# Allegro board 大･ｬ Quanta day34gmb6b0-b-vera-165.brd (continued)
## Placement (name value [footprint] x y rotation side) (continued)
PC76  *22U/6.3V_8  [CC0805]  103.4 51.36 0 top
PC77  0.1U/10V_4  [CC0402]  69.24 45.26 270 top
PC78  *10U/6.3V_6  [CC0603]  67.84 44.37 270 top
PC79  0.1U/10V_4  [CC0402]  66.19 44.12 180 top
PC80  *0.1U/10V_4  [CC0402]  63.27 42.09 0 top
PC82  1000P/50V_4  [CC0402]  70.76 41.45 180 top
PC85  0.1U/10V_4  [CC0402]  63.27 40.95 0 top
PC86  1000P/50V_4  [CC0402]  70.76 40.44 180 top
PC87  *0.1U/10V_4  [CC0402]  63.27 39.93 0 top
PC90  0.1U/25V_4  [CC0402]  94.77 45.64 180 top
PC92  0.1U/10V_4  [CC0402]  65.56 38.02 90 top
PC93  *10U/6.3V_6  [CC0603]  95.02 42.98 0 top
PC95  *10U/6.3V_6  [CC0603]  67.71 37.77 90 top
PC96  0.1U/10V_4  [CC0402]  69.24 37.64 90 top
PC98  10U/6.3V_6  [CC0603]  93.8 41.2 0 top
PC101  0.1U/10V_4  [CC0402]  69.24 34.85 270 top
PC103  *10U/6.3V_6  [CC0603]  67.71 34.09 270 top
PC104  0.1U/10V_4  [CC0402]  65.43 33.71 270 top
PC105  1U/6.3V_4  [CC0402]  102.21 38.68 180 top
PC106  0.033U/10V_4  [CC0402]  92.78 38.66 0 top
PC107  0.1U/10V_4  [CC0402]  92.78 37.64 0 top
PC108  *0.1U/10V_4  [CC0402]  63.27 31.8 0 top
PC109  1000P/50V_4  [CC0402]  69.75 31.29 180 top
PC110  0.1U/10V_4  [CC0402]  63.27 30.79 0 top
PC111  1000P/50V_4  [CC0402]  69.75 30.28 180 top
PC112  *0.1U/10V_4  [CC0402]  63.27 29.77 0 top
PC113  *0.1U/10V_4  [CC0402]  95.12 35.23 90 top
PC114  *0.1U/10V_4  [CC0402]  98.58 35.23 90 top
PC115  0.1U/10V_4  [CC0402]  65.56 27.86 90 top
PC116  *10U/6.3V_6  [CC0603]  67.71 27.61 90 top
PC117  0.1U/10V_4  [CC0402]  69.24 27.1 90 top
PC118  2200P/50V_4  [CC0402]  89.58 181.58 90 bottom
PC119  0.1U/50V_6  [CC0603]  89.53 179.26 270 bottom
PC124  10U/25V_8  [CC0805]  120.52 177.6 90 bottom
PC126  0.1U/25V_4  [CC0402]  121.03 179.91 180 bottom
PC127  0.1U/25V_4  [CC0402]  124.23 181.38 90 bottom
PC128  10U/25V_8  [CC0805]  118.41 177.62 90 bottom
PC130  0.1U/25V_4  [CC0402]  116.76 177.8 90 bottom
PC164  22U/6.3V_8  [CC0805]  115.34 113.21 270 bottom
PC165  22U/6.3V_8  [CC0805]  117.37 113.21 270 bottom
PC166  *22U/6.3V_8  [CC0805]  112.6 112.5 0 bottom
PC167  *100U/25V  [ECAP6D3S]  181.68 123.5 270 bottom
PC168  *2200P/50V_4  [CC0402]  112.29 98.86 180 bottom
PC169  4.7U/25V_8  [CC0805]  100.48 91.75 270 top
PC170  *4.7U/25V_8  [CC0805]  102.51 91.75 270 top
PC171  0.1U/25V_4  [CC0402]  98.96 90.98 270 bottom
PC172  2200P/50V_4  [CC0402]  102.89 85.98 180 bottom
PC173  0.01U/25V_4  [CC0402]  93.88 86.16 90 bottom
PC174  0.01U/50V_4  [CC0402]  95.65 85.65 0 bottom
PC175  22U/6.3V_8  [CC0805]  182.93 78 270 bottom
PC176  *22U/6.3V_8  [CC0805]  190.14 78.16 270 bottom
PC177  22U/6.3V_8  [CC0805]  188.11 78.16 270 bottom
PC178  22U/6.3V_8  [CC0805]  186.08 78.16 270 bottom
PC179  0.1U/10V_4  [CC0402]  184.45 77.62 270 bottom
PC180  0.1U/25V_4  [CC0402]  191.16 72.82 90 bottom
PC181  1U/6.3V_4  [CC0402]  193.57 71.68 90 bottom
PC182  0.1U/10V_4  [CC0402]  194.59 71.68 270 bottom
PC183  *0.1U/10V_4  [CC0402]  198.25 67.49 270 bottom
PC184  *2200P/50V_4  [CC0402]  188.62 66.6 0 bottom
PC185  4.7U/25V_8  [CC0805]  193.44 64.19 0 bottom
PC186  *150U/6.3V_5X3.8 ESR20  [ECAP5X5_8-5_9-2P]  185.57 63.68 90 bottom
PC187  0.1U/25V_4  [CC0402]  48.16 58.22 90 bottom
PC188  0.1U/25V_4  [CC0402]  53.24 58.09 90 bottom
PC189  0.1U/25V_4  [CC0402]  41.04 57.71 180 bottom
PC190  *100U/25V  [ECAP6D3S]  35.82 57.03 0 bottom
PC191  2200P/50V_4  [CC0402]  41.04 56.69 180 bottom
PC192  2200P/50V_4  [CC0402]  48.16 55.04 180 bottom
PC193  4.7U/25V_8  [CC0805]  42.06 54.92 0 bottom
PC194  0.1U/25V_4  [CC0402]  94.03 57.91 180 bottom
PC195  0.1U/25V_4  [CC0402]  48.16 54.03 180 bottom
PC196  4.7U/25V_8  [CC0805]  42.06 52.88 0 bottom
PC197  4.7U/25V_8  [CC0805]  97.36 56.67 180 bottom
PC198  4.7U/6.3V_6  [CC0603]  56.79 52.5 0 bottom
PC199  *2200P/50V_4  [CC0402]  38.48 52.3 0 bottom
PC200  0.1U/25V_4  [CC0402]  33.68 52.25 180 bottom
PC201  *150U/6.3V_5X3.8 ESR20  [ECAP5X5_8-5_9-2P]  102.54 40.31 90 bottom
PC202  4.7U/25V_8  [CC0805]  47.76 51.72 90 bottom
PC203  4.7U/25V_8  [CC0805]  49.79 51.72 90 bottom
PC204  0.01U/50V_4  [CC0402]  56.54 51.36 180 bottom
PC205  4.7U/6.3V_6  [CC0603]  44.98 49.96 90 bottom
PC206  *2200P/50V_4  [CC0402]  46.12 49.84 90 bottom
PC207  4.7U/25V_8  [CC0805]  95.58 54.66 180 bottom
PC208  22U/6.3V_8  [CC0805]  102.06 53.57 0 bottom
PC209  *0.1U/10V_4  [CC0402]  56.54 48.31 0 bottom
PC210  0.1U/25V_4  [CC0402]  97.51 58.27 0 bottom
PC211  *0.1U/10V_4  [CC0402]  40.28 47.04 180 bottom
PC212  2200P/50V_4  [CC0402]  95.91 58.73 90 bottom
PC213  0.1U/25V_4  [CC0402]  57.43 46.79 90 bottom
PC214  6800P/50V_4  [CC0402]  44.02 46.53 90 bottom
PC215  22U/6.3V_8  [CC0805]  103.27 51.56 0 bottom
PC216  2.2U/6.3V_6  [CC0603]  45.12 46.28 270 bottom
PC217  *2200P/50V_4  [CC0402]  102.33 49.53 90 bottom
PC218  *150U/6.3V_5X3.8 ESR20  [ECAP5X5_8-5_9-2P]  46.76 40.31 90 bottom
PC219  *150U/6.3V_5X3.8 ESR20  [ECAP5X5_8-5_9-2P]  41.3 40.3 90 bottom
PC220  0.1U/10V_4  [CC0402]  29.74 39.68 270 bottom
PC221  22U/6.3V_8  [CC0805]  31.27 39.55 90 bottom
PC222  22U/6.3V_8  [CC0805]  33.3 39.55 90 bottom
PC223  *22U/6.3V_8  [CC0805]  37.54 39.55 90 bottom
PC224  22U/6.3V_8  [CC0805]  35.33 39.55 90 bottom
PC225  22U/6.3V_8  [CC0805]  57.17 38.28 90 bottom
PC226  22U/6.3V_8  [CC0805]  52.86 38.28 90 bottom
PC227  22U/6.3V_8  [CC0805]  55.01 38.28 90 bottom
PC228  *22U/6.3V_8  [CC0805]  50.57 38.28 90 bottom
PC229  0.1U/10V_4  [CC0402]  58.82 38.02 270 bottom
PC230  0.1U/10V_4  [CC0402]  101.01 56.26 0 bottom
PC231  0.1U/25V_4  [CC0402]  79.88 172.34 180 bottom
PC232  100P/50V_4  [CC0402]  86.63 179.86 0 top
PC233  *0.1U/50V_6  [CC0603]  86.86 181.27 0 top
PC234  0.047U/25V_4  [CC0402]  95.19 181.13 0 top
PC235  2200P/50V_4  [CC0402]  108.91 180.85 270 top
PC236  0.1U/25V_4  [CC0402]  92 173.48 180 top
PC237  0.1U/25V_4  [CC0402]  88.74 174.86 0 top
PC238  0.1U/25V_4  [CC0402]  91 174.5 0 top
PC239  1U/25V_4  [CC0402]  94.28 177.58 270 top
PC240  0.1U/25V_4  [CC0402]  92.4 183.95 180 top
PC241  0.1U/25V_4  [CC0402]  104.56 186.16 0 top
PC242  1000P/50V_4  [CC0402]  104.55 185.14 180 top
PC243  2200P/50V_4  [CC0402]  104.52 184.1 180 top
PC244  0.01U/50V_4  [CC0402]  102.05 178.19 270 bottom
PC250  2200P/50V_4  [CC0402]  53.82 162 270 top
PC251  0.1U/10V_4  [CC0402]  55.04 167.97 180 top
PC252  *10U/6.3V_6  [CC0603]  58.37 163.68 180 top
PC253  0.1U/10V_4  [CC0402]  58.52 162.38 180 top
PC254  100U/25V  [ECAP6D3S]  98.5 168.05 90 bottom
PD1  PDZ5.6B  [DSM]  119.77 184.11 180 top
PD2  PDZ5.6B  [DSM]  119.77 182.08 180 top
PD4  RB501V-40  [DSM]  97.78 179.17 270 top
PD7  1N4448WS-7-F  [DSM]  67.9 179.6 0 bottom
PD8  RB501V-40  [DSM]  103.45 176.12 270 bottom
PD9  SMAJ20A-13-F  [D-DO-214AC]  80.11 174.22 0 bottom
PD10  SMAJ20A-13-F  [D-DO-214AC]  45.36 56.19 270 bottom
PD11  UDZVTE-173.6B  [DSM]  57.2 53.65 180 top
PJP1  *POWER_JP/S  [SHORT-SOLDERJUMPER-3]  180.52 77.42 135 bottom
PJP2  *POWER_JP/S  [SHORT-SOLDERJUMPER-3]  103.78 56.06 45 bottom
PJP3  *POWER_JP/S  [SHORT-SOLDERJUMPER-3]  29.95 43.25 135 bottom
PJP4  *POWER_JP/S  [SHORT-SOLDERJUMPER-3]  58.32 42.22 45 bottom
PL1  *80/5A  [RC0805]  172.36 121.34 270 top
PL2  1uH/2.6A_2520  [L3_2X2_5-1_55]  183.41 66.22 180 top
PL3  *0_8/S  [SHORT0805]  196.75 62.03 180 top
PL4  *0_8/S  [SHORT0805]  69.11 183.69 180 bottom
PL5  *0_8/S  [SHORT0805]  121.72 183.54 180 bottom
PL6  *0_8/S  [SHORT0805]  69.11 181.66 180 bottom
PL7  *0_8/S  [SHORT0805]  121.72 181.51 180 bottom
PL8  4.7uH/5.5A(PCMC063T-4R7MN)  [CHOKE-MPL73-1R5]  109.36 176.84 0 bottom
PL14  0.36uH  [CHOKE-ETQP4L]  112.29 105.72 0 bottom
PL15  *0_8/S  [SHORT0805]  102 87.68 180 bottom
PL16  1uH/11A(PCMC063T-1R0MN)  [CHOKE-MPL73-1R5]  186.33 72.19 180 bottom
PL17  *0_8/S  [SHORT0805]  43.08 57.71 270 bottom
PL18  *0_8/S  [SHORT0805]  50.95 57.71 270 bottom
PL19  *0_8/S  [SHORT0805]  94 56.67 0 bottom
PL20  2.2uH/8A(PCMC063T-2R2MN)  [CHOKE-MPL73-1R5]  35.58 47.3 270 bottom
PL21  1.5uH/9A(PCMC063T-1R5MN)  [CHOKE-MPL73-1R5]  53.24 44.25 270 bottom
PL22  1uH/11A(PCMC063T-1R0MN)  [CHOKE-MPL73-1R5]  96.29 45.01 0 bottom
PQ1  DMN601K-7  [SOT23_213-3_3-2]  115.37 181.82 90 top
PQ5  DMN601K-7  [SOT23_213-3_3-2]  175.79 130.35 180 top
PQ6  BSS138W  [UMT_213-3-1_3]  171.6 128.58 180 top
PQ9  *DMN601K-7  [SOT23_213-3_3-2]  171.47 125.4 0 top
PQ10  FDMC8884  [PG-TSDSON-8-8P-R]  175.28 121.84 270 top
PQ12  DRC5144E0L  [UMT_213-3-1_3]  39.9 98.32 270 top
PQ13  DRC5144E0L  [UMT_213-3-1_3]  42.54 98.25 90 top
PQ14  *DRC5144E0L  [UMT_213-3-1_3]  37.23 98.22 90 top
PQ15  *FDMS0308AS  [SO-8FL-5P]  108.13 97.09 180 top
PQ16  *2N7002KDW  [SC70-2_1-65-6P]  37.36 94.29 270 top
PQ17  *2N7002KDW  [SC70-2_1-65-6P]  42.82 94.29 270 top
PQ18  *DRC5144E0L  [UMT_213-3-1_3]  47.14 94.29 90 top
PQ19  *FDMS7698  [SO-8FL-5P]  106.84 89.05 90 top
PQ20  QM3016D  [TO252_134-9_9-4_57-SMT]  78.99 179.12 0 bottom
PQ29  FDMS0308AS  [SO-8FL-5P]  108.13 97.07 180 bottom
PQ30  FDMS7698  [SO-8FL-5P]  106.83 89.05 90 bottom
PQ31  FDMC7692S  [PG-TSDSON-8-8P-R]  97.92 51.16 90 bottom
PQ32  FDMC8884  [PG-TSDSON-8-8P-R]  94.16 51.08 270 bottom
PQ33  EMB20P03V  [PG-TSDSON-8-8P-R]  72.97 180.85 0 bottom
PQ34  DMN601K-7  [SOT23_213-3_3-2]  81.68 178.62 270 top
PQ35  METR3904-G  [SOT23_213-3_3-2]  77.92 178.64 90 top
PQ36  FDMC8884  [PG-TSDSON-8-8P-R]  102.28 179.63 0 top
PQ37  FDMC8884  [PG-TSDSON-8-8P-R]  106.55 180.01 90 top
PQ38  MMDT2907A-7-F  [SOT363-2_1-65-6P]  70.79 176.35 90 bottom
PQ39  FDMS7698  [SO-8FL-5P]  96.81 179.38 0 bottom
PQ40  METR3904-G  [SOT23_213-3_3-2]  59.33 56.46 180 top
PQ41  *DMN601K-7  [SOT23_213-3_3-2]  46.33 162.97 270 top
PQ42  DRC5144E0L  [UMT_213-3-1_3]  43.28 159.11 270 top
PQ43  EMB32N03K  [TSOP6-2_8-95]  54.18 165.1 180 top
PQ44  DMN601K-7  [SOT23_213-3_3-2]  50.09 161.06 270 top
PR1  330_4  [RC0402]  124.48 186.74 0 top
PR2  330_4  [RC0402]  126.64 186.74 180 top
PR3  1K/F_4  [RC0402]  128.29 186.23 90 top
PR4  200K_4  [RC0402]  129.69 186.23 270 top
PR7  470_8  [RC0805]  119.91 180.14 0 top
PR9  4.02K/F_4  [RC0402]  101.9 175.08 90 bottom
PR11  22_8  [RC0805]  97.18 183.52 0 top
PR12  10/F_4  [RC0402]  86.66 178.82 180 top
PR13  *0_4/S  [SHORT0402]  85.82 176.56 270 top
PR14  2.2_6  [RC0603]  109.02 178.38 90 top
PR15  *0_4/S  [SHORT0402]  86.84 176.56 270 top
PR16  430K/F_4  [RC0402]  84.53 181 180 top
PR17  88.7K/F_4  [RC0402]  84.55 179.88 0 top
PR18  43.2K/F_4  [RC0402]  88.03 176.56 90 top
PR19  0_6  [RC0603]  95.43 179.6 0 top
PR20  1M_4  [RC0402]  81.51 176.02 0 top
PR21  1M_4  [RC0402]  81.51 174.98 0 top
PR22  4.02K/F_4  [RC0402]  92.89 181.53 90 bottom
PR52  1M_4  [RC0402]  172.74 131.5 180 top
PR55  1M_4  [RC0402]  172.74 130.48 0 top
PR56  2M_4  [RC0402]  174.01 127.31 90 top
PR57  1M_4  [RC0402]  175.03 127.31 270 top
PR61  *22_8  [RC0805]  170.33 121.34 270 top
PR62  *1M_4  [RC0402]  35.33 97.59 270 top
PR63  *0_4/S  [SHORT0402]  44.47 96.06 90 top
PR64  *1M_4  [RC0402]  40.54 94.79 180 top
PR65  *1M_4  [RC0402]  35.33 95.56 270 top
PR66  *1M_4  [RC0402]  40.54 95.81 180 top
PR67  *0_4/S  [SHORT0402]  39.52 93.78 180 top
PR68  2.43K/F_6  [RC0603]  44.47 93.65 90 top
PR69  2.43K/F_6  [RC0603]  41.12 92.99 270 top
PR70  1_6  [RC0603]  95.78 88.82 270 top
PR71  16.2K/F_4  [RC0402]  91.72 88.7 0 top
PR72  *0_4/S  [SHORT0402]  95.65 83.36 180 bottom
PR73  *0_4/S  [SHORT0402]  91.72 87.68 180 top
PR74  1K/F_4  [RC0402]  98.83 87.68 180 top
PR75  10/F_4  [RC0402]  88.92 86.41 0 top
PR76  *0_4/S  [SHORT0402]  98.83 86.41 0 top
PR77  *10K/F_4  [RC0402]  100.86 86.41 180 top
PR78  54.9/F_4  [RC0402]  98.83 85.4 0 top
PR79  *0_4/S  [SHORT0402]  100.86 85.4 0 top
PR80  64.9K/F_6  [RC0603]  87.15 85.14 270 top
PR81  *75/F_4  [RC0402]  98.83 84.38 0 top
PR82  *0_4/S  [SHORT0402]  100.86 84.38 0 top
PR83  130/F_4  [RC0402]  98.83 83.36 0 top
PR84  *0_4/S  [SHORT0402]  100.86 83.36 0 top
PR85  165K/F_4  [RC0402]  87.15 82.73 90 top
PR86  *0_4/S  [SHORT0402]  98.83 82.35 0 top
PR87  *75/F_4  [RC0402]  100.86 82.35 0 top
PR88  23.7K/F_4  [RC0402]  91.59 81.46 0 bottom
PR89  *0_4/S  [SHORT0402]  98.83 81.33 0 top
PR90  75K/F_4  [RC0402]  86.13 81.33 270 top
PR91  *0_4  [RC0402]  98.83 80.32 180 top
PR92  15.4K/F_4  [RC0402]  88.92 82.22 180 top
PR93  18.7K/F_4  [RC0402]  93.24 81.46 90 bottom
PR94  1K/F_4  [RC0402]  92.23 78.66 90 top
PR95  49.9/F_4  [RC0402]  93.24 78.66 90 top
PR96  0_4  [RC0402]  94.26 78.66 90 top
PR97  2.2_6  [RC0603]  98.58 78.41 90 top
PR98  6.04K/F_4  [RC0402]  90.19 77.65 270 top
PR99  0_4  [RC0402]  91.72 76.12 0 top
PR100  0_4  [RC0402]  96.29 76.63 90 top
PR101  0_4  [RC0402]  97.31 76.63 90 top
PR102  *0_4  [RC0402]  197 67.28 0 top
PR103  100K/F_4  [RC0402]  197.25 65.58 180 top
PR104  *0_6/S  [SHORT0603]  183.11 63.73 180 top
PR105  100K/F_4  [RC0402]  190.02 62.28 0 top
PR106  *0_4/S  [SHORT0402]  192.09 62.28 0 top
PR107  *0_4/S  [SHORT0402]  190.02 61.14 0 top
PR108  150K/F_4  [RC0402]  192.17 61.14 0 top
PR109  *0_2/S  [SHORT0201]  181.63 68.05 90 top
PR110  *0_4/S  [SHORT0402]  57.25 50.29 0 top
PR111  10K/F_4  [RC0402]  57.25 49.28 0 top
PR112  *0_4/S  [SHORT0402]  57.25 48.26 180 top
PR113  *0_4/S  [SHORT0402]  63.26 43.16 180 top
PR114  *0_8/S  [SHORT0805]  70.38 43.1 180 top
PR117  *0_6/S  [SHORT0603]  70 39.29 0 top
PR118  *0_4/S  [SHORT0402]  63.27 38.91 0 top
PR119  2.2_6  [RC0603]  95.02 44.37 180 top
PR122  301K/F_4  [RC0402]  102.21 39.7 0 top
PR123  *0_2/S  [SHORT0201]  93.83 39.65 180 top
PR124  *0_4/S  [SHORT0402]  63.27 32.82 180 top
PR125  *0_8/S  [SHORT0805]  70.38 32.82 180 top
PR126  100/F_4  [RC0402]  94.31 38.15 270 top
PR127  *0_2/S  [SHORT0201]  101.67 37.52 90 top
PR128  10.2K/F_4  [RC0402]  92.22 35.87 0 top
PR129  *0_4/S  [SHORT0402]  93.8 35.23 90 top
PR130  *0_4/S  [SHORT0402]  99.59 35.23 90 top
PR131  620K/F_4  [RC0402]  100.61 35.23 270 top
PR132  *0_4/S  [SHORT0402]  102.13 35.23 90 top
PR133  *0_6/S  [SHORT0603]  70 29.01 0 top
PR134  10K/F_4  [RC0402]  92.22 34.72 0 top
PR135  *0_4/S  [SHORT0402]  63.27 28.75 0 top
PR136  *0_2/S  [SHORT0201]  114.78 176.4 270 bottom
PR137  RC1206-R010  [F3_2X1_65-2_8]  114.91 177.09 90 bottom
PR138  *0_2/S  [SHORT0201]  114.78 177.85 90 bottom
PR143  12.4K/F_4  [RC0402]  62.76 182.04 180 bottom
PR144  75K/F_4  [RC0402]  64.87 181.94 0 bottom
PR158  *0_2/S  [SHORT0201]  109.62 105.84 180 bottom
PR159  *0_2/S  [SHORT0201]  114.96 105.84 0 bottom
PR160  220K_4 NTC  [RC0402]  105.18 102.29 90 bottom
PR161  *2.2_6  [RC0603]  112.29 99.97 0 bottom
PR162  TSM0B104F4251RZ  [RC0402]  110.51 92.89 270 bottom
PR163  69.8K/F_4  [RC0402]  91.59 84.51 180 bottom
PR164  100K/F_4  [RC0402]  91.59 83.49 0 bottom
PR165  0_6  [RC0603]  192.3 73.08 90 bottom
PR166  *0_4/S  [SHORT0402]  197.25 69.01 180 bottom
PR167  *0_2/S  [SHORT0201]  196.62 67.87 270 bottom
PR168  *2.2_6  [RC0603]  188.62 67.87 180 bottom
PR169  *0_4/S  [SHORT0402]  198.25 65.35 90 bottom
PR170  *0_2/S  [SHORT0201]  188.11 76.51 90 bottom
PR171  3.16K/F_4  [RC0402]  195.73 64.19 90 bottom
PR172  10.2K/F_4  [RC0402]  196.75 64.19 90 bottom
PR173  499K/F_4  [RC0402]  55.27 55.42 180 bottom
PR174  150K/F_4  [RC0402]  55.27 54.41 0 bottom
PR175  0_6  [RC0603]  31.77 52.25 90 bottom
PR176  *2.2_6  [RC0603]  36.07 52.17 0 bottom
PR177  1K/F_4  [RC0402]  56.54 50.34 180 bottom
PR178  0_6  [RC0603]  58.19 49.58 270 bottom
PR179  1M_4  [RC0402]  56.54 49.33 180 bottom
PR180  *2.2_6  [RC0603]  48.28 46.79 180 bottom
PR181  *0_4/S  [SHORT0402]  41.81 46.53 270 bottom
PR182  1K/F_4  [RC0402]  43.01 46.54 90 bottom
PR183  1M_4  [RC0402]  40.28 46.03 0 bottom
PR184  1K/F_4  [RC0402]  40.28 45.01 0 bottom
PR185  *1K/F_4  [RC0402]  42.31 45.01 180 bottom
PR186  *2.2_6  [RC0603]  100.35 50.09 270 bottom
PR187  *0_2/S  [SHORT0201]  43.31 43.74 180 bottom
PR188  *0_2/S  [SHORT0201]  58.82 39.68 180 bottom
PR189  *0_2/S  [SHORT0201]  104.67 54.15 180 bottom
PR206  1M_4  [RC0402]  72.64 174.7 90 bottom
PR207  220K_4  [RC0402]  69.06 176.35 270 bottom
PR208  1K_6  [RC0603]  67.84 178 0 bottom
PR209  220K_4  [RC0402]  67.89 176.4 270 bottom
PR210  1M_4  [RC0402]  72.64 176.76 270 bottom
PR211  RC1206-R010  [F3_2X1_65-2_8]  96.14 174.09 270 bottom
PR212  4.02K/F4  [RC0402]  90.77 184.49 270 top
PR213  69.8K/F_4  [RC0402]  82.49 181.27 0 top
PR214  100K/F_4  [RC0402]  89.12 176.55 90 top
PR215  127K/F_4  [RC0402]  80.26 181.27 0 top
PR216  750K/F_4  [RC0402]  78.13 181.29 180 top
PR217  100K/F_4  [RC0402]  89.1 184 0 top
PR218  100K/F_4  [RC0402]  89.1 185.04 0 top
PR219  5.6/F_6  [RC0603]  90.35 176.32 90 top
PR220  10/F_6  [RC0603]  91.62 176.37 90 top
PR221  *0_2/S  [SHORT0201]  96.01 174.73 90 bottom
PR222  *0_2/S  [SHORT0201]  96.01 173.46 270 bottom
PR223  4.99K/F_4  [RC0402]  56.13 55.93 180 top
PR224  4.02K/F_4  [RC0402]  56.13 56.95 0 top
PR237  *22_8  [RC0805]  46.3 166.47 0 top
PR245  1M_4  [RC0402]  45.39 159.84 90 top
PR246  1M_4  [RC0402]  46.61 159.84 90 top
PR247  1M_4  [RC0402]  50.09 164.54 90 top
PR248  5.1M_4  [RC0402]  52.63 162 90 top
PU1  BQ24738H  [PVQFN20-3_5X3_5-5-25P]  90.96 180.62 180 top
PU3  NCP81101MNTXG  [QFN28-4X4-4-29P-NCP81101MNTWG]  93.62 84 180 top
PU4  APW8824  [TSOP6-2_8-95]  187.22 63.81 90 top
PU5  APL3523A  [SON14-3X2-4-15P]  66.7 40.95 270 top
PU7  RT8231BGQW  [WQFN20-3X3-4-21P]  97.86 39.68 270 top
PU8  APL3523A  [SON14-3X2-4-15P]  66.7 30.79 270 top
PU10  G5335AQT1U  [QFN23-4X4-5]  193.42 67.95 180 bottom
PU11  SY8208B  [QFN10-3X3-45]  52.98 50.6 180 bottom
PU12  SY8208C  [QFN10-3X3-45]  41.93 49.71 90 bottom
Q1  DDTC144EUA-7-F  [UMT_213-3-1_3]  25.04 171.88 180 top
Q3  2N7002DW  [SC70-2_1-65-6P]  192.94 159.19 0 top
Q4  DRC5144E0L  [UMT_213-3-1_3]  170.69 155.98 90 top
Q5  *DRC5144E0L  [UMT_213-3-1_3]  173.35 155.98 90 top
Q10  2N7002  [SOT23_213-3_3-2]  19.94 94.36 0 top
Q12  2N7002DW  [SC70-2_1-65-6P]  181 90.7 0 top
Q13  2N7002K  [SOT23_213-3_3-2]  36.98 90.22 180 top
Q14  2N7002DW  [SC70-2_1-65-6P]  25.4 87.78 180 top
Q15  METR3904-G  [SOT23_213-3_3-2]  56.03 86.92 270 top
Q16  METR3904-G  [SOT23_213-3_3-2]  33.04 81.71 90 top
Q17  ME2303T1  [SOT23_213-3_3-2]  190.4 79.05 180 top
Q18  2N7002E  [SOT23_213-3_3-2]  190.65 73.84 270 top
Q19  2N7002  [SOT23_213-3_3-2]  178.08 63.81 0 top
Q20  AO3404  [SOT23_213-3_3-2]  166.65 135.81 0 top
Q21  2N7002  [SOT23_213-3_3-2]  169.7 131.88 270 top
Q22  2N7002K  [SOT23_213-3_3-2]  22.12 37.9 180 top
Q23  *METR3904-G  [SOT23_213-3_3-2]  108.48 23.42 90 top
Q24  2N7002  [SOT23_213-3_3-2]  138.58 22.53 0 top
Q25  2N7002K  [SOT23_213-3_3-2]  147.6 21.9 270 top
Q26  DRC5144E0L  [UMT_213-3-1_3]  143.15 21.64 270 top
Q27  2N7002KDW  [SC70-2_1-65-6P]  160.81 20.88 180 top
Q28  *DRC5144E0L  [UMT_213-3-1_3]  37.84 15.19 180 top
Q29  *MMBT3904  [SOT23_213-3_3-2]  171.35 9.58 270 top
Q30  *DRC5144E0L  [UMT_213-3-1_3]  37.97 8.92 270 top
Q31  2N7002  [SOT23_213-3_3-2]  176.15 6.66 270 top
Q34  2N7002DW  [SC70-2_1-65-6P]  168.43 9.58 90 top
Q37  2N7002K  [SOT23_213-3_3-2]  195.2 101.17 90 top
Q38  *2N7002DW  [SC70-2_1-65-6P]  185.09 97.38 180 bottom
Q39  AO3404  [SOT23_213-3_3-2]  191.54 93.4 90 bottom
Q40  2N7002K  [SOT23_213-3_3-2]  15.64 73.33 270 bottom
Q41  2N7002DW  [SC70-2_1-65-6P]  194.89 100.25 270 bottom
Q820  2N7002DW  [SC70-2_1-65-6P]  165.38 7.93 0 top
Q821  2N7002DW  [SC70-2_1-65-6P]  155.34 6.78 0 top
Q7030  *2N7002K  [SOT23_213-3_3-2]  39.39 180.26 270 bottom
Q7031  *ME2303T1  [SOT23_213-3_3-2]  48.92 180.65 0 bottom
R1  1K_4  [RC0402]  41.55 165.28 270 top
R2  0_4  [RC0402]  43.58 165.28 90 top
R4  100K/F_4  [RC0402]  43.08 166.93 180 top
R5  1K/F_4  [RC0402]  43.08 168.07 180 top
R6  100K/F_4  [RC0402]  43.08 170.36 0 top
R7  *0_4/S  [SHORT0402]  40.66 170.36 180 top
R19  0_4  [RC0402]  64.51 174.62 270 top
R21  330_4  [RC0402]  18.57 173.91 0 top
R27  10_4  [RC0402]  60.76 172.57 270 top
R28  1K/F_4  [RC0402]  61.31 174.24 180 top
R31  100K/F_4  [RC0402]  55.97 178.36 0 bottom
R39  *100K_4  [RC0402]  56.03 172.57 270 top
R40  *100K_4  [RC0402]  57.3 172.57 270 top
R57  10K/F_4  [RC0402]  25.68 176.33 0 top
R58  1K_4  [RC0402]  59.59 172.57 270 top
R74  10K_4  [RC0402]  195.54 161.01 0 top
R90  *0_6  [RC0603]  195.93 159.11 270 top
R91  *0_4  [RC0402]  184.05 159.82 0 top
R94  *0_4  [RC0402]  176.05 159.31 90 top
R95  10K_4  [RC0402]  185.82 159.18 270 top
R96  10K/F_4  [RC0402]  170.97 158.93 90 top
R101  75/F_4  [RC0402]  15.57 161.85 270 top
R119  75/F_4  [RC0402]  15.59 156.25 90 top
R124  *0_4  [RC0402]  19.35 150.04 0 top
R125  *0_4  [RC0402]  19.35 148.95 0 top
R127  *0_4  [RC0402]  19.35 147.83 0 top
R128  *0_4  [RC0402]  19.35 146.74 0 top
R131  75/F_4  [RC0402]  15.75 140.89 270 top
R139  *10K_4  [RC0402]  184.07 106.65 270 top
R140  75/F_4  [RC0402]  15.75 135.33 90 top
R142  *0_4/S  [SHORT0402]  25.04 121.97 180 top
R143  *0_4  [RC0402]  17.07 121.16 270 top
R144  1K_4  [RC0402]  18.41 121.16 90 top
R145  15K/F_4  [RC0402]  18.03 119.61 180 top
R146  *0_4/S  [SHORT0402]  17.98 118.57 180 top
R147  *0_4/S  [SHORT0402]  154.58 117.03 90 top
R148  10K/F_4  [RC0402]  145.11 115.27 180 top
R149  3.01K/F_4  [RC0402]  156.74 112.95 90 top
R150  3.01K/F_4  [RC0402]  158.14 112.95 90 top
R151  *0_8  [RC0805]  18.31 113.16 0 top
R152  10K/F_4  [RC0402]  145.69 112.83 270 top
R153  *1M_4  [RC0402]  153.32 112.45 0 top
R154  2.49K/F_4  [RC0402]  25.8 112.07 270 top
R155  *10/F_4  [RC0402]  22.56 111.39 270 top
R156  *0_4  [RC0402]  21.49 108.26 270 top
R157  0_4  [RC0402]  21.49 110.41 90 top
R158  10K_4  [RC0402]  175.03 96.44 0 bottom
R159  *0_4/S  [SHORT0402]  24.65 104.8 180 top
R160  10K_4  [RC0402]  185.44 103.68 90 top
R161  *10K_4  [RC0402]  186.71 103.68 90 top
R162  100K_4 NTC  [RC0402]  24.66 102.29 180 top
R163  *10K_4  [RC0402]  185.44 101.65 90 top
R164  10K_4  [RC0402]  186.71 101.65 90 top
R165  24.9/F_4  [RC0402]  155.6 100 0 top
R166  1K_4  [RC0402]  196.26 97.16 0 top
R167  10K_4  [RC0402]  185.82 96.83 180 top
R168  10K_4  [RC0402]  182.65 93.9 270 top
R169  10K_4  [RC0402]  173.76 95.3 270 top
R170  1M_4  [RC0402]  22.6 95 90 top
R171  *0_4  [RC0402]  159.54 94.96 270 top
R172  10K_4  [RC0402]  185.24 94.49 180 top
R173  10K_4  [RC0402]  174.78 95.3 270 top
R174  10K_4  [RC0402]  180.36 93.9 90 top
R175  10K_4  [RC0402]  181.51 93.9 90 top
R176  20K/F_4  [RC0402]  17.4 93.85 90 top
R177  *0_4  [RC0402]  184.25 95.53 180 top
R178  *0_4/S  [SHORT0402]  177.82 93.14 180 top
R179  *0_4/S  [SHORT0402]  159.54 92.92 90 top
R180  10K_4  [RC0402]  184.5 92.68 90 top
R181  10K_4  [RC0402]  190.52 92.13 90 top
R182  4.7K_4  [RC0402]  49.43 92 270 top
R183  10K_4  [RC0402]  176.17 91.87 180 top
R184  1K_4  [RC0402]  153.44 91.62 270 top
R185  4.7K_4  [RC0402]  178.2 91.36 270 top
R186  10K_4  [RC0402]  176.17 90.86 180 top
R187  2.2K_4  [RC0402]  24.76 90.2 90 top
R188  2.2K_4  [RC0402]  26.41 90.2 90 top
R189  4.7K_4  [RC0402]  33.68 89.84 270 top
R190  4.7K_4  [RC0402]  49.43 89.84 90 top
R191  *10K_4  [RC0402]  51.59 89.84 90 top
R192  1K_4  [RC0402]  176.93 89.84 0 top
R193  22.6/F_4  [RC0402]  161.82 88.95 0 top
R194  4.7K_4  [RC0402]  180.62 89.08 0 top
R195  10K_4  [RC0402]  177.7 88.82 180 top
R196  2.2K_4  [RC0402]  17.42 88.57 0 top
R197  4.7K_4  [RC0402]  38 87.81 180 top
R198  *10K_4  [RC0402]  178.84 87.81 180 top
R199  10K_4  [RC0402]  181.51 87.81 0 top
R200  47K/F_4  [RC0402]  36.47 87.3 90 top
R201  51_4  [RC0402]  115.34 87.3 0 top
R202  2.2K_4  [RC0402]  17.42 87.05 0 top
R203  4.7K_4  [RC0402]  38 86.79 180 top
R204  10K_4  [RC0402]  179.47 86.79 0 top
R205  *10K_4  [RC0402]  181.51 86.79 180 top
R206  43_4  [RC0402]  38.12 85.78 0 top
R207  10K/F_4  [RC0402]  33.58 85.75 270 top
R208  33_4  [RC0402]  68.48 85.65 90 top
R209  *0_4/S  [SHORT0402]  69.49 85.65 270 top
R210  *0_4  [RC0402]  115.34 85.65 0 top
R211  10K_4  [RC0402]  180.87 85.65 0 top
R212  15/F_4  [RC0402]  52.35 92.89 270 top
R213  *0_4  [RC0402]  36.47 85.01 270 top
R214  470/F_4  [RC0402]  19.45 84.89 0 top
R215  *0_4/S  [SHORT0402]  17.41 84.85 0 top
R216  4.7K_4  [RC0402]  38.12 84.51 180 top
R217  120/F_4  [RC0402]  15.77 84.38 270 top
R218  10K_4  [RC0402]  180.98 84.26 180 top
R219  *0_4/S  [SHORT0402]  17.41 83.84 0 top
R220  15/F_4  [RC0402]  53.49 86.03 270 top
R221  *0_4  [RC0402]  55.4 83.74 180 top
R222  470/F_4  [RC0402]  19.45 83.62 0 top
R223  *10K/F_4  [RC0402]  36.85 83.36 0 top
R224  10K/F_4  [RC0402]  49.05 83.24 270 top
R225  15/F_4  [RC0402]  51.2 92.89 270 top
R226  15/F_4  [RC0402]  53.49 92.89 270 top
R227  *0_4/S  [SHORT0402]  38.76 82.98 90 top
R228  10K/F_4  [RC0402]  53.24 82.6 0 top
R229  4.7K_4  [RC0402]  55.4 82.6 180 top
R230  470/F_4  [RC0402]  17.3 82.35 180 top
R231  120/F_4  [RC0402]  15.77 81.71 270 top
R232  470/F_4  [RC0402]  17.3 81.08 180 top
R233  470/F_4  [RC0402]  17.3 80.06 180 top
R234  120/F_4  [RC0402]  15.77 79.43 270 top
R235  22K/F_4  [RC0402]  22.4 77.78 270 top
R236  80.6K/F_4  [RC0402]  23.42 77.78 90 top
R237  100K_4  [RC0402]  32.41 79.12 180 top
R238  10K_4  [RC0402]  163.22 79.05 180 top
R239  10K/F_4  [RC0402]  165.25 79.05 180 top
R240  10K_4  [RC0402]  167.41 79.05 0 top
R241  470/F_4  [RC0402]  17.3 78.79 180 top
R242  22_4  [RC0402]  160.3 78.28 90 top
R243  *0_4  [RC0402]  161.44 78.54 90 top
R245  10K/F_4  [RC0402]  165.25 78.03 180 top
R246  470/F_4  [RC0402]  17.3 77.78 180 top
R247  120/F_4  [RC0402]  15.77 77.14 270 top
R248  *10K_4  [RC0402]  165.25 77.01 0 top
R249  100/F_4  [RC0402]  126.93 76.89 90 top
R250  121/F_4  [RC0402]  127.94 76.89 90 top
R251  200/F_4  [RC0402]  128.96 76.89 90 top
R252  360/F_4  [RC0402]  67.33 76.76 180 top
R253  470/F_4  [RC0402]  17.3 76.51 180 top
R254  22_4  [RC0402]  162.96 76 180 top
R255  10K_4  [RC0402]  165.25 76 0 top
R256  20K/F_4  [RC0402]  167.28 76 180 top
R257  200K_4  [RC0402]  193.06 75.87 270 top
R258  100K_4  [RC0402]  169.72 77.34 0 top
R259  1K_4  [RC0402]  179.73 75.74 90 top
R260  4.7K_4  [RC0402]  32.74 76.68 90 top
R261  10K/F_4  [RC0402]  56.28 75.36 90 top
R262  1K_4  [RC0402]  77.87 75.36 90 top
R263  1K_4  [RC0402]  79.91 75.36 270 top
R264  *51_4  [RC0402]  80.92 75.36 90 top
R265  *0_6  [RC0603]  168.43 74.35 180 top
R266  470_4  [RC0402]  157 76.98 270 top
R267  10K_4  [RC0402]  193.06 73.84 270 top
R268  10K_4  [RC0402]  178.61 73.63 90 top
R269  10K_4  [RC0402]  179.75 73.63 90 top
R270  1K_4  [RC0402]  85.53 73.61 0 top
R271  *0_4  [RC0402]  87.78 73.2 180 top
R272  *10_4  [RC0402]  34.97 73.08 270 top
R273  100K/F_4  [RC0402]  15.77 72.95 0 top
R274  *0_4/S  [SHORT0402]  27.07 72.57 90 top
R275  *0_4  [RC0402]  28.09 72.57 90 top
R276  16.5K/F_4  [RC0402]  24.66 98.22 180 top
R277  20K/F_4  [RC0402]  168.43 73.08 180 top
R278  *0_4  [RC0402]  178.08 71.43 180 top
R279  *10K_4  [RC0402]  56.16 70.92 0 top
R280  3.3K/F_4  [RC0402]  24.66 100.25 0 top
R281  *0_4/S  [SHORT0402]  34.57 70.54 270 top
R282  10K_4  [RC0402]  178.08 70.41 0 top
R283  *0_4  [RC0402]  180.11 70.41 180 top
R284  10K_4  [RC0402]  56.16 69.77 180 top
R285  4.7K_4  [RC0402]  56.16 67.36 0 top
R286  *0_4  [RC0402]  86.89 66.09 0 top
R287  *0_4  [RC0402]  86.89 64.95 180 top
R288  1K_4  [RC0402]  68.98 64.69 0 top
R289  1K_4  [RC0402]  74.95 64.69 180 top
R290  *1K_4  [RC0402]  79.53 64.19 90 top
R291  *0_4  [RC0402]  56.16 63.42 180 top
R292  0_4  [RC0402]  81.68 63.3 180 top
R293  10K_4  [RC0402]  181.25 62.54 180 top
R294  2K_4  [RC0402]  56.16 62.41 0 top
R295  0_4  [RC0402]  81.68 62.03 180 top
R296  *0_4/S  [SHORT0402]  181.25 61.52 180 top
R297  0_4  [RC0402]  81.68 61.01 180 top
R298  100/F_4  [RC0402]  56.16 60.12 180 top
R299  4.7K_4  [RC0402]  187.35 54.66 180 top
R300  0_4  [RC0402]  81.68 59.74 180 top
R301  4.7K_4  [RC0402]  189.51 54.66 180 top
R302  *1K_4  [RC0402]  195.35 59.36 270 top
R303  1M_4  [RC0402]  172.36 133.15 90 top
R304  12.1K/F_4  [RC0402]  56.16 58.98 180 top
R305  *0_4/S  [SHORT0402]  21.36 58.73 0 top
R306  *0_4/S  [SHORT0402]  21.36 57.71 0 top
R307  *0_4/S  [SHORT0402]  21.36 56.57 0 top
R308  *0_4/S  [SHORT0402]  182.88 58.37 270 top
R309  *0_4/S  [SHORT0402]  189.43 56.82 180 top
R310  *0_4/S  [SHORT0402]  21.36 55.55 0 top
R312  *0_4/S  [SHORT0402]  21.36 54.15 0 top
R314  *0_4/S  [SHORT0402]  21.36 53.14 0 top
R315  2M_4  [RC0402]  167.16 132.77 270 top
R316  *0_4/S  [SHORT0402]  37.16 53.77 270 top
R317  *0_4/S  [SHORT0402]  36.02 53.77 270 top
R318  *0_4  [RC0402]  84.1 49.71 270 top
R319  1.8K/F_4  [RC0402]  111.02 48.57 0 top
R320  1.8K/F_4  [RC0402]  111.02 47.42 180 top
R321  10K/F_4  [RC0402]  174.78 47.42 270 top
R322  *0_4/S  [SHORT0402]  19.56 47.4 0 top
R323  10K/F_4  [RC0402]  173.12 47.3 0 top
R324  *0_4/S  [SHORT0402]  19.56 46.25 0 top
R326  *4.7K/F_6  [RC0603]  194.84 44.42 180 top
R328  4.99K/F_6  [RC0603]  194.84 43.23 180 top
R329  *0_4/S  [SHORT0402]  19.71 42.09 0 top
R330  *0_4/S  [SHORT0402]  19.71 41.07 0 top
R331  2/F_6  [RC0603]  109.62 40.56 0 top
R332  66.5/F_4  [RC0402]  149.88 39.29 270 top
R333  66.5/F_4  [RC0402]  151.15 39.29 270 top
R334  10K/F_4  [RC0402]  175.41 39.29 90 top
R335  10K/F_4  [RC0402]  19.58 38.53 90 top
R336  24.9/F_4  [RC0402]  109.5 38.15 180 top
R337  0_6  [RC0603]  194.84 38.15 180 top
R338  10_8  [RC0805]  181.89 37.52 180 top
R339  64.9K/F_6  [RC0603]  17.17 37.52 270 top
R340  10K/F_4  [RC0402]  172.62 37.39 0 top
R341  10K/F_6  [RC0603]  194.84 36.88 180 top
R342  *0/J_6S  [SHORT0603]  92.1 16.56 90 bottom
R343  24.3K/F_6  [RC0603]  190.4 36.25 180 top
R344  *100K/F_4  [RC0402]  183.28 35.33 90 top
R345  *0_4/S  [SHORT0402]  184.68 35.71 90 top
R346  *0_4/S  [SHORT0402]  185.7 35.74 90 top
R347  10K/F_6  [RC0603]  192.28 35.53 270 top
R348  10K/F_4  [RC0402]  172.62 36.37 0 top
R349  24.9/F_4  [RC0402]  111.91 34.47 270 top
R350  2/F_6  [RC0603]  114.45 34.47 90 top
R351  1.8K/F_4  [RC0402]  118.26 34.47 270 top
R352  1.8K/F_4  [RC0402]  119.4 34.47 90 top
R353  *100K/F_4  [RC0402]  184.68 33.68 90 top
R354  *100K/F_4  [RC0402]  185.7 33.71 90 top
R355  100K/F_6  [RC0603]  187.6 33.45 180 top
R356  4.7K_4  [RC0402]  186.08 29.9 0 top
R357  *4.7K_4  [RC0402]  195.1 29.39 90 top
R358  *4.7K_4  [RC0402]  196.11 29.39 90 top
R359  *4.7K_4  [RC0402]  194.08 29.13 90 top
R360  4.7K_4  [RC0402]  186.08 28.88 0 top
R361  *4.7K_4  [RC0402]  186.08 27.86 0 top
R362  *4.7K_4  [RC0402]  195.98 27.86 180 top
R363  4.7K_4  [RC0402]  186.08 26.85 0 top
R364  *4.7K_4  [RC0402]  195.98 26.85 180 top
R365  *0_4  [RC0402]  79.93 26.57 180 top
R366  66.5/F_4  [RC0402]  149.36 25.92 90 top
R367  66.5/F_4  [RC0402]  150.5 25.92 90 top
R368  *0_4  [RC0402]  86.38 24.82 0 top
R369  5.36K_4  [RC0402]  189.13 24.82 90 top
R370  1.8K/F_4  [RC0402]  152.83 36.17 180 top
R371  24.9/F_4  [RC0402]  155.09 25.58 0 top
R372  6.2K/F_4  [RC0402]  66.83 22.91 270 top
R373  *2M/F_4  [RC0402]  150.01 23.09 90 top
R374  10K_4  [RC0402]  184.17 22.53 90 top
R375  *0_4  [RC0402]  86.38 22.53 0 top
R376  *4.7K/F_4  [RC0402]  74.7 22.28 180 top
R377  33_4  [RC0402]  58.19 22.15 270 top
R378  33_4  [RC0402]  59.21 22.15 270 top
R379  1.8K/F_4  [RC0402]  151.53 25.07 270 top
R380  2/F_6  [RC0603]  152.32 26.67 0 top
R381  100K_4  [RC0402]  141.25 21.9 270 top
R382  *0_4  [RC0402]  108.86 32.69 0 top
R383  220K_4  [RC0402]  108.86 33.71 180 top
R384  *0_4  [RC0402]  86.38 21.51 0 top
R385  *0_4  [RC0402]  74.7 21.26 180 top
R386  *10K/F_4  [RC0402]  110.01 20.75 0 top
R387  *0_4/S  [SHORT0402]  191.79 20.75 270 top
R388  *0_4/S  [SHORT0402]  194.97 20.75 270 top
R389  *8.2K_4  [RC0402]  36.47 20.63 180 top
R390  33_4  [RC0402]  57.68 20.63 0 top
R391  *33_4  [RC0402]  86.38 20.5 0 top
R392  *4.7K/F_4  [RC0402]  74.7 20.24 0 top
R393  *8.2K_4  [RC0402]  36.47 19.48 180 top
R394  *0_4  [RC0402]  86.38 19.48 0 top
R395  600_300mA  [RC0402]  179.22 18.17 90 top
R396  33_4  [RC0402]  57.68 18.59 0 top
R397  200/F_6  [RC0603]  38.25 18.34 0 top
R398  33_4  [RC0402]  57.68 17.58 0 top
R399  *0_4  [RC0402]  86.38 17.2 0 top
R400  200/F_6  [RC0603]  38.25 17.07 0 top
R401  4.7K_4  [RC0402]  165.12 21.26 90 top
R402  33_4  [RC0402]  57.68 16.56 0 top
R403  4.7K_4  [RC0402]  165.12 19.23 270 top
R404  *0_4  [RC0402]  163.73 14.4 270 top
R405  600_300mA  [RC0402]  178.84 14.53 180 top
R406  10K_4  [RC0402]  62.25 13.64 90 top
R407  *0_4/S  [SHORT0402]  64.29 13.64 90 top
R408  *2.2K_4  [RC0402]  169.59 12.62 270 top
R409  *200/F_6  [RC0603]  37.49 13.13 0 top
R410  33_4  [RC0402]  177.32 11.99 90 top
R411  *0_4/S  [SHORT0402]  178.84 12.37 180 top
R412  4.7K_4  [RC0402]  159.41 16.69 270 top
R413  *1K/F_4  [RC0402]  39.39 12.36 90 top
R414  *200/F_6  [RC0603]  37.49 11.86 0 top
R415  4.7K_4  [RC0402]  159.41 18.72 90 top
R416  *0_4  [RC0402]  155.22 9.7 180 top
R417  100K_4  [RC0402]  152.42 9.7 180 top
R418  *100K_4  [RC0402]  165.38 10.34 90 top
R419  0_4  [RC0402]  164.36 10.34 90 top
R420  *10K_4  [RC0402]  171.14 13.08 180 top
R421  10K_4  [RC0402]  171.14 12.07 0 top
R422  *1K/F_4  [RC0402]  35.57 8.69 0 top
R423  0_4  [RC0402]  153.06 8.43 0 top
R424  0_4  [RC0402]  158.9 6.78 90 top
R425  0_4  [RC0402]  160.17 6.78 90 top
R426  0_4  [RC0402]  164.62 6.27 180 top
R427  100K/F_4  [RC0402]  179.47 7.8 90 top
R428  39.2K/F_4  [RC0402]  181.51 7.8 90 top
R429  20K/F_4  [RC0402]  183.79 7.8 90 top
R430  2.2K_4  [RC0402]  184.81 7.8 90 top
R431  *0_4/S  [SHORT0402]  173.76 7.04 90 top
R432  10K_4  [RC0402]  178.46 5.77 270 top
R433  10K_4  [RC0402]  180.49 5.77 90 top
R434  10K_4  [RC0402]  181.51 5.77 90 top
R435  2.2K_4  [RC0402]  185.32 5.77 270 top
R436  1K/F_4  [RC0402]  186.33 5.77 270 top
R439  *0_6/S  [SHORT0603]  18.69 177.6 0 bottom
R440  1K/F_4  [RC0402]  61.95 172.57 270 top
R444  330_4  [RC0402]  18.57 168.58 0 top
R454  *0_6/S  [SHORT0603]  15.39 159.82 270 bottom
R458  4.7K_4  [RC0402]  192.84 153.24 90 bottom
R482  4.7K_4  [RC0402]  134.57 115.24 90 bottom
R483  100K_4  [RC0402]  166.27 115.24 180 bottom
R484  8.2K/F_4  [RC0402]  161.19 114.73 270 bottom
R485  3.01K/F_4  [RC0402]  162.2 114.73 90 bottom
R486  10K_4  [RC0402]  168.81 114.73 270 bottom
R487  *10K/F_4  [RC0402]  166.27 114.22 180 bottom
R488  15/F_4  [RC0402]  180.36 111.94 0 bottom
R489  15/F_4  [RC0402]  180.36 110.67 180 bottom
R490  15/F_4  [RC0402]  180.36 109.65 180 bottom
R491  3.3K/F_4  [RC0402]  179.86 108.13 90 bottom
R492  100K_4  [RC0402]  179.35 106.6 180 bottom
R493  *10K_4  [RC0402]  179.35 105.46 180 bottom
R494  10K_4  [RC0402]  121.56 105.33 0 bottom
R495  10K/F_4  [RC0402]  121.56 104.32 180 bottom
R496  *51_4  [RC0402]  121.56 103.3 180 bottom
R497  1M_4  [RC0402]  191.67 102.41 270 bottom
R498  2M_4  [RC0402]  192.68 102.41 270 bottom
R499  10K_4  [RC0402]  182.52 102.84 90 bottom
R500  3.3K/F_4  [RC0402]  186.08 102.67 180 bottom
R501  100/F_4  [RC0402]  121.56 102.29 0 bottom
R502  *0_4  [RC0402]  183.54 102.03 90 bottom
R503  *0_4/S  [SHORT0402]  184.55 101.98 270 bottom
R504  15/F_4  [RC0402]  186.08 101.65 0 bottom
R505  15/F_4  [RC0402]  188.11 101.65 180 bottom
R506  51_4  [RC0402]  123.98 100.58 180 bottom
R507  15/F_4  [RC0402]  189.63 101.4 90 bottom
R508  100/F_4  [RC0402]  121.56 100.89 0 bottom
R509  *51_4  [RC0402]  121.56 99.87 0 bottom
R510  *10K_4  [RC0402]  172.74 100.38 180 bottom
R511  10K_4  [RC0402]  177.67 99.87 180 bottom
R512  *10K_4  [RC0402]  179.22 99.49 270 bottom
R513  10K_4  [RC0402]  180.36 99.49 270 bottom
R514  10K_4  [RC0402]  181.38 99.49 270 bottom
R515  10K_4  [RC0402]  182.4 99.49 270 bottom
R516  10K_4  [RC0402]  183.41 99.49 270 bottom
R517  56.2/F_4  [RC0402]  124.48 99.37 180 bottom
R518  10K_4  [RC0402]  172.74 99.37 180 bottom
R519  10K_4  [RC0402]  175.03 98.98 0 bottom
R520  10K_4  [RC0402]  177.32 98.48 180 bottom
R521  130/F_4  [RC0402]  124.48 98.22 180 bottom
R522  62_4  [RC0402]  121.44 98.1 0 bottom
R523  10K_4  [RC0402]  172.74 98.22 180 bottom
R524  10K_4  [RC0402]  175.03 97.59 0 bottom
R525  10K_4  [RC0402]  177.06 97.33 180 bottom
R526  8.2K/F_4  [RC0402]  179.22 97.33 90 bottom
R527  10K_4  [RC0402]  180.36 97.33 270 bottom
R528  10K_4  [RC0402]  181.51 97.33 270 bottom
R529  10K_4  [RC0402]  182.52 97.33 270 bottom
R530  10K_4  [RC0402]  187.73 97.33 270 bottom
R531  43_4  [RC0402]  124.48 97.08 0 bottom
R532  22_8  [RC0805]  192.17 97.08 270 bottom
R533  75/F_4  [RC0402]  122.07 96.57 90 bottom
R534  10K_4  [RC0402]  172.74 97.08 180 bottom
R535  10K_4  [RC0402]  183.34 105.05 0 top
R536  10K_4  [RC0402]  177.06 96.19 0 bottom
R537  49.9/F_4  [RC0402]  124.48 95.94 0 bottom
R538  10K_4  [RC0402]  172.74 96.06 0 bottom
R539  *10K_4  [RC0402]  179.22 95.17 270 bottom
R540  *10K_4  [RC0402]  180.24 95.17 270 bottom
R541  10K_4  [RC0402]  181.25 95.17 270 bottom
R542  1K_4  [RC0402]  121.44 94.92 0 bottom
R543  *1K_4  [RC0402]  124.48 94.79 0 bottom
R544  100K_4  [RC0402]  176.93 94.79 180 bottom
R545  *10K_4  [RC0402]  172.74 94.92 0 bottom
R546  10K_4  [RC0402]  174.9 94.03 180 bottom
R547  51_4  [RC0402]  121.44 93.65 180 bottom
R548  51_4  [RC0402]  124.48 93.65 180 bottom
R549  *10K_4  [RC0402]  186.59 93.52 180 bottom
R550  10K_4  [RC0402]  176.43 93.14 270 bottom
R551  10K_4  [RC0402]  177.44 93.14 270 bottom
R552  10K_4  [RC0402]  174.9 93.02 180 bottom
R553  *0_4  [RC0402]  172.74 93.78 0 bottom
R554  *51_4  [RC0402]  121.44 92.51 180 bottom
R555  *10K_4  [RC0402]  112.85 92.33 270 bottom
R556  150/F_4  [RC0402]  113.87 92.33 90 bottom
R557  10K_4  [RC0402]  114.88 92.33 90 bottom
R558  10K_4  [RC0402]  175.16 90.86 270 bottom
R559  *10K_4  [RC0402]  176.17 90.86 90 bottom
R560  2.2K_4  [RC0402]  177.44 90.86 270 bottom
R561  10K_4  [RC0402]  178.46 90.86 90 bottom
R562  51_4  [RC0402]  121.44 90.73 180 bottom
R563  100K_4  [RC0402]  181.89 90.6 270 bottom
R564  *51_4  [RC0402]  121.44 89.59 180 bottom
R565  10K_4  [RC0402]  175.66 89.33 180 bottom
R566  2.2K_4  [RC0402]  177.44 88.82 270 bottom
R567  10K_4  [RC0402]  175.66 88.32 180 bottom
R568  2.2K_4  [RC0402]  178.97 88.06 0 bottom
R569  2.2K_4  [RC0402]  178.97 87.05 0 bottom
R570  2.2K_4  [RC0402]  179.47 86.03 0 bottom
R571  10K_4  [RC0402]  181 85.9 270 bottom
R572  2.2K_4  [RC0402]  179.47 85.01 0 bottom
R573  *10M_4  [RC0402]  176.55 76 180 top
R574  *1K_4  [RC0402]  163.22 78.03 180 bottom
R575  330K_4  [RC0402]  165.25 77.65 270 bottom
R576  330K_4  [RC0402]  166.27 77.65 90 bottom
R577  1M_4  [RC0402]  167.28 77.65 270 bottom
R578  10K_4  [RC0402]  168.43 77.65 270 bottom
R579  *0_4  [RC0402]  169.44 77.65 90 bottom
R580  51_4  [RC0402]  118.51 77.52 0 bottom
R581  1K_4  [RC0402]  161.69 77.52 270 bottom
R582  *0_4/S  [SHORT0402]  174.52 74.98 0 top
R583  49.9/F_4  [RC0402]  158.42 77.09 270 bottom
R584  49.9/F_4  [RC0402]  159.43 77.09 270 bottom
R585  33_4  [RC0402]  163.22 77.01 180 bottom
R586  *0_4/S  [SHORT0402]  171.47 76.33 270 bottom
R587  *0_4  [RC0402]  23.14 76.51 0 bottom
R588  10K_4  [RC0402]  170.97 78.16 180 bottom
R589  33_4  [RC0402]  162.58 76 0 bottom
R590  33_4  [RC0402]  164.62 76 0 bottom
R591  33_4  [RC0402]  166.65 76 0 bottom
R592  *0_4  [RC0402]  19.71 72.95 180 bottom
R593  100K_4  [RC0402]  170.46 76.15 270 bottom
R594  *0_4  [RC0402]  23.14 75.49 0 bottom
R595  10K/F_4  [RC0402]  25.42 72.44 90 bottom
R596  10K/F_4  [RC0402]  18.69 70.66 180 bottom
R597  10K/F_4  [RC0402]  18.69 71.93 180 bottom
R598  *0_8  [RC0805]  18.06 53.39 270 bottom
R599  *0_8  [RC0805]  20.09 53.39 270 bottom
R600  *0_8  [RC0805]  22.12 53.39 270 bottom
R601  *0_4/S  [SHORT0402]  92.48 25.58 270 top
R602  10K/J_4  [RC0402]  91.34 25.58 90 top
R603  *0/J_8S  [SHORT0805]  92.48 34.34 270 bottom
R604  0_4  [RC0402]  162.58 5.13 180 top
R605  *15K/F_4  [RC0402]  161.69 6.66 270 top
R608  0_4  [RC0402]  186.43 20.24 180 bottom
R609  *0_4  [RC0402]  188.36 16.43 0 bottom
R610  *0_4/S  [SHORT0402]  174.22 8.31 90 bottom
R611  2K/F_4  [RC0402]  198.4 16.56 180 bottom
R612  2K/F_4  [RC0402]  198.4 15.55 180 bottom
R613  100K/F_4  [RC0402]  200.94 14.78 0 bottom
R614  *0_4/S  [SHORT0402]  193.63 13.41 90 bottom
R615  *0_4/S  [SHORT0402]  196.75 13.51 90 bottom
R616  *0_4  [RC0402]  191.41 13.01 0 bottom
R617  *0_4  [RC0402]  198.27 13.01 180 bottom
R618  *0_8/S  [SHORT0805]  187.35 12.07 0 bottom
R621  0_6  [RC0603]  189.76 48.95 180 top
R622  0_4  [RC0402]  192.81 20.88 90 bottom
R623  0_4  [RC0402]  193.95 20.88 90 bottom
R624  *0_4  [RC0402]  191.54 13.01 180 top
R625  *0_4  [RC0402]  191.54 14.15 180 top
R626  10K_4  [RC0402]  175.79 95.3 270 top
R627  100K/F_4  [RC0402]  167.92 13.39 0 top
R628  0_6  [RC0603]  186.46 48.95 0 top
R7465  *220K_4  [RC0402]  42.7 181.92 180 bottom
R7466  *10K/F_4  [RC0402]  42.19 180.14 270 bottom
R7467  0_6  [RC0603]  44.22 180.65 180 bottom
R7469  *10K/F_4  [RC0402]  171.35 76 0 top
R7470  100K/F_4  [RC0402]  184.81 31.38 0 bottom
R7471  *0_4  [RC0402]  176.81 75.62 180 bottom
R7472  0_4  [RC0402]  177.52 77.74 90 bottom
R7473  0_4  [RC0402]  172.49 77.27 270 bottom
R7478  *10K_4  [RC0402]  144.17 10.47 0 top
R7479  47K/F_4  [RC0402]  152.17 6.27 0 top
R7481  10K/F_4  [RC0402]  166.65 10.34 270 top
R7482  47K/F_4  [RC0402]  152.17 5.13 180 top
R7484  100K_4  [RC0402]  167.92 12.24 180 top
R7487  10K/F_4  [RC0402]  152.17 7.29 0 top
R8512  4.7K_4  [RC0402]  58.47 168.61 0 top
R8513  *4.7K_4  [RC0402]  58.47 165.02 0 top
R8514  *4.7K_4  [RC0402]  67.82 170.18 180 top
R8515  5.36K_4  [RC0402]  64.39 172.49 270 top
R8516  4.7K_4  [RC0402]  67.82 166.55 180 top
R8517  *4.7K_4  [RC0402]  58.47 169.82 0 top
R8518  4.7K_4  [RC0402]  58.47 166.22 0 top
R8519  *4.7K_4  [RC0402]  58.47 167.41 0 top
R8520  *4.7K_4  [RC0402]  67.82 167.77 180 top
R8521  *4.7K_4  [RC0402]  67.82 168.99 180 top
R8546  0_4  [RC0402]  73.15 164.01 180 top
R8547  0_4  [RC0402]  73.15 162.81 180 top
R8548  0_4  [RC0402]  73.15 165.46 180 top
R8549  0_4  [RC0402]  73.15 166.65 180 top
R8550  0_4  [RC0402]  71.22 170.54 90 top
R8551  0_4  [RC0402]  69.95 170.54 90 top
R8552  0.1U/10V_4  [RC0402]  73.76 170.54 90 top
R8553  0.1U/10V_4  [RC0402]  72.49 170.54 90 top
R8554  4.7K_4  [RC0402]  55.19 72.44 90 top
R8558  0_4  [RC0402]  52.78 62.03 0 top
R8559  *0_4  [RC0402]  54.57 63.75 270 top
R8560  10K_4  [RC0402]  186.71 99.49 270 top
R8561  *0_4  [RC0402]  186.71 105.73 90 top
R8562  0_4  [RC0402]  185.44 105.73 90 top
R8563  0_4  [RC0402]  155.34 5.13 0 top
R8564  0_4  [RC0402]  166.67 6.1 180 top
RP1  *0_4P2R_4  [4P2R-0404]  147.47 112.83 180 top
RP2  10K_10P8R_6  [10P8R]  181.81 107.24 180 top
RP3  *10P8R-8.2K  [10P8R]  26.44 43.61 270 top
RP4  *10P8R-8.2K  [10P8R]  26.44 39.68 270 top
RP5  10K_10P8R_6  [10P8R]  176.43 102.67 0 bottom
RP6  10K_10P8R_6  [10P8R]  180.11 102.67 0 bottom
TP3  *PAD  [TP2650]  16.03 121.54 0 top
TP4  *  [TP2650]  154.68 115.34 0 top
TP5  *  [TP2650]  149.96 117.45 0 top
TP6  *PAD  [TP2650]  22.57 113.37 0 top
TP7  *  [TP2675]  161.31 99.87 0 top
TP8  *  [TP2675]  162.33 94.26 0 top
TP9  *  [TP2675]  160.3 91.11 0 top
TP10  *  [TP2050]  163.73 77.9 0 top
TP11  *  [TP2050]  54.51 67.74 0 top
TP12  *  [TP2650]  188.87 59.36 270 top
TP13  *  [TP2650]  98.07 16.18 0 top
TP20  *  [TP2050]  140.94 109.88 180 bottom
TP21  *  [TP2650]  169.95 114.35 180 bottom
TP22  *  [TP2650]  171.22 114.35 180 bottom
TP23  *  [TP2675]  185.56 112.94 0 top
TP24  *  [TP2675]  182.38 113.1 0 top
TP25  *  [TP2050]  178.99 109 180 bottom
TP26  *  [TP2650]  119.91 105.21 180 bottom
TP27  *  [TP2650]  119.91 103.94 180 bottom
TP28  *  [TP2675]  186.37 115.86 0 top
TP29  *  [TP2675]  185.7 100.64 180 bottom
TP30  *  [TP2675]  183.77 116.57 0 top
TP31  *  [TP2050]  125.34 100.38 180 bottom
TP32  *  [TP2650]  179.09 83.87 180 bottom
TP33  *  [TP2650]  180.36 83.87 180 bottom
TP34  *  [TP2650]  125.25 77.52 180 bottom
TP35  *  [TP2675]  175.94 78 180 bottom
TP36  *  [TP2650]  125.25 76 180 bottom
TP51  *  [TP1250-P14_4]  163.98 87.94 0 top
U2  AP2821KTR-G1  [SOT23-5]  54.38 180.65 0 bottom
U6  NS681684  [TRF-9_6-1_27-16P]  22.25 159.06 270 top
U7  NS681684  [TRF-9_6-1_27-16P]  22.2 138.09 270 top
U8  RTL8161GSH  [QFN32-4X4-4-33P-0_9H]  22.88 117.02 90 top
U9  SLG3NB3454  [TQFN16-2X3-4-17P]  70 81.59 270 top
U10  TPS2546  [QFN16-3X3-5-17P-WM9001]  23.26 74.22 0 top
U11  IT8987E/AX  [LQFP128-16X16-4]  44.6 71.93 270 top
U12  *SN74CBTLV3126RGYR  [VQFN14-3_5X3_5-5-15P]  87.15 69.9 180 top
U13  HP3DC2TR  [LGA16-3X3-5-HP3DC2TR]  186.38 57.4 0 top
U14  TPA3113D2  [TSSOP28-6_4-65-29P-1_2H]  188.49 40.95 0 top
U15  PS8713BTQFN24GTR2-A1  [TQFN24-4X4-5-34P]  190.02 28.88 270 top
U16  *EMC1412-1-ACZL-TR  [MSOP8-4_9-65]  115.59 22.28 270 top
U17  *TPS793475DBVR  [SOT23-5]  186.33 21.01 90 top
U18  *SLB9656TT1.2  [TSSOP28-6_4-65]  80.54 20.88 270 top
U19  RTS5237  [QFN32-4X4-5-33P-RTS5227-GRT]  62.38 18.21 180 top
U20  ALC3241 x QFN48  [QFN48-7X7-5-49P-1H]  184.43 13.26 270 top
U21  TPA2012D2  [PWQFN20-4X4-5-30P]  159.54 10.72 270 top
U22  *TLV70233DBVR  [SOT23-5]  144.04 7.8 90 top
U23  *A25LQ32AM-F/Q  [91960-0084L-8P-SOCKET]  185.57 109.02 180 bottom
U24  GD25B64BSIGR  [SOIC8-8-1_27]  185.57 109.02 180 bottom
U25  *HSW_ULT_DDR3L  [BGA1168-INTEL-HASWELL]  148.6 94.2 0 bottom
U26  IC(5P) G5243AT11U-Lay  [SOT23-5]  183.67 94.06 270 bottom
U27  UP7534BRA8-20  [MSOP8-4_9-65]  18.82 45.9 180 bottom
U28  HPA022642RTJR  [PWQFN20-4X4-5-30P]  194.59 17.2 180 bottom
U8021  PS8713BTQFN24GTR2-A1  [TQFN24-4X4-5-34P]  63.14 167.82 90 top
VC1  *TVM0G5R5M220R  [CC0402]  15.37 93.85 270 top
VC2  *TVM0G5R5M220R  [CC0402]  23.62 90.2 270 top
VC3  *AVLC5S_4  [CC0402]  17.42 52.76 90 top
VC4  *AVLC5S_4  [CC0402]  18.44 58.6 0 bottom
VC5  *AVLC5S_4  [CC0402]  19.71 41.33 90 bottom
VC6  *AVLC5S_4  [CC0402]  62.86 90.93 0 top
Y1  *24MHZ +-30PPM  [XTL-3_2X2_5-2_2X1_7-0_8H]  152.21 116.37 90 top
Y2  *25MHZ +-10PPM  [XTL-3_2X2_5-2_2X1_7]  24.62 107.28 270 top
Y3  25MHZ +-10PPM  [XTL-3_2X2_5-2_2X1_7]  75.28 81.74 270 top
Y4  *32.768KHz  [XTL-3_2X1_5-2_5-0_8H]  175.41 73.33 0 top

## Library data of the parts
BAT14 = BAT-PMPCRT-08MLBK2ZZ4H0-8P-L
BAT15 = BAT-PMPCRT-08MLBK2ZZ4H1-8P-L
BAT17 = 88513-2001-20P-L
C2 C10 C12 C21 C23 C25 C27 C28 C30-C33 C35-C37 C40 C49 C50 C52 C58 C60 C69-C72 C91 C92 C97 C98 C103-C106 C109 C110 C114 C115 C120 C175 C225-C237 C243-C250 C256 C257 C259 C261-C266 C273 C281 C282 C288-C294 C296-C298 C305-C311 C313-C329 C331-C346 C349-C352 C354-C397 C399 C401-C405 C408 C409 C417 C420 C424 C425 C427 C428 C430-C433 C435-C444 C446-C457 C459 C461-C463 C465 C466 C468-C472 C474-C476 C479-C489 C491-C500 C505-C509 C511-C513 C515 C516 C519 C521-C530 C533-C542 C545-C549 C551 C552 C554-C559 C561-C565 C567-C580 C582-C587 C589-C594 C597-C599 C614 C641 C644 C647 C649 C651 C653 C698 C701-C705 C707 C708 C710-C720 C722-C734 C739-C741 C745 C746 C748-C763 C765-C772 C774 C777-C780 C782 C786 C787 C793-C800 C803-C806 C1028 C7747 C7748 C8738 C8739 C8742-C8744 C8746 C8776-C8785 EC1-EC10 EC12 EC13 EC17-EC36 EC38-EC44 EC46-EC71 EC73-EC82 EC85 EC87-EC92 PC1 PC5 PC7 PC9-PC11 PC34 PC35 PC37 PC39 PC45 PC46 PC50 PC53-PC63 PC65-PC69 PC71-PC73 PC77 PC79 PC80 PC82 PC85-PC87 PC90 PC92 PC96 PC101 PC104-PC115 PC117 PC118 PC126 PC127 PC130 PC168 PC171-PC174 PC179-PC184 PC187-PC189 PC191 PC192 PC194 PC195 PC199 PC200 PC204 PC206 PC209-PC214 PC217 PC220 PC229-PC232 PC234-PC244 PC250 PC251 PC253 VC1-VC6 = CC0402
C48 C125 C238-C242 C251-C255 C258 C260 C267-C272 C274-C280 C283-C287 C295 C299-C304 C312 C330 C347 C398 C400 C412-C416 C418 C419 C423 C434 C458 C460 C464 C467 C477 C478 C490 C501-C504 C510 C518 C531 C532 C543 C544 C550 C553 C560 C566 C581 C588 C595 C596 C650 C652 C694-C697 C699 C700 C706 C721 C735-C738 C742-C744 C773 C775 C776 C801 C802 C810 C1027 EC37 EC45 PC13 PC38 PC51 PC52 PC64 PC74 PC78 PC93 PC95 PC98 PC103 PC116 PC119 PC198 PC205 PC216 PC233 PC252 = CC0603
C101 C102 C406 C407 C410 C411 C421 C422 C473 EC11 EC14-EC16 EC84 EC86 PC12 PC41-PC44 PC47-PC49 PC70 PC75 PC76 PC124 PC128 PC164-PC166 PC169 PC170 PC175-PC178 PC185 PC193 PC196 PC197 PC202 PC203 PC207 PC208 PC215 PC221-PC228 = CC0805
C514 C520 PR13 PR15 PR63 PR67 PR72 PR73 PR76 PR79 PR82 PR84 PR86 PR89 PR106 PR107 PR110 PR112 PR113 PR118 PR124 PR129 PR130 PR132 PR135 PR166 PR169 PR181 R7 R142 R146 R147 R159 R178 R179 R209 R215 R219 R227 R274 R281 R296 R305-R310 R312 R314 R316 R317 R322 R324 R329 R330 R345 R346 R387 R388 R407 R411 R431 R503 R582 R586 R601 R610 R614 R615 = SHORT0402
C517 = D-SOD523-1_2X0_8-0_7H
C608 = CC1808
C747 C764 PC167 PC190 PC254 = ECAP6D3S
C8745 C8774 C8775 C8786 L25 L30-L35 L37 L38 L42 L47 L58 PR1-PR4 PR9 PR12 PR16-PR18 PR20-PR22 PR52 PR55-PR57 PR62 PR64-PR66 PR71 PR74 PR75 PR77 PR78 PR81 PR83 PR85 PR87 PR88 PR90-PR96 PR98-PR103 PR105 PR108 PR111 PR122 PR126 PR128 PR131 PR134 PR143 PR144 PR160 PR162-PR164 PR171-PR174 PR177 PR179 PR182-PR185 PR206 PR207 PR209 PR210 PR212-PR218 PR223 PR224 PR245-PR248 R1 R2 R4-R6 R19 R21 R27 R28 R31 R39 R40 R57 R58 R74 R91 R94-R96 R101 R119 R124 R125 R127 R128 R131 R139 R140 R143-R145 R148-R150 R152-R158 R160-R177 R180-R208 R210-R214 R216-R218 R220-R226 R228-R243 R245-R264 R266-R273 R275-R280 R282-R295 R297-R304 R315 R318-R321 R323 R332-R336 R340 R344 R348 R349 R351-R354 R356-R379 R381-R386 R389-R396 R398 R399 R401-R406 R408 R410 R412 R413 R415-R430 R432-R436 R440 R444 R458 R482-R502 R504-R531 R533-R581 R583-R585 R587-R597 R602 R604 R605 R608 R609 R611-R613 R616 R617 R622-R627 R7465 R7466 R7469-R7473 R7478 R7479 R7481 R7482 R7484 R7487 R8512-R8521 R8546-R8554 R8558-R8564 = RC0402
CN2 = 51540-0404T-001-40P-L
CN3 CN31 = 88266-0400-4P-L
CN5 CN12 CN16 = 88513-0601-6P-L-SMT
CN6 = 88266-020L-2P-L-SMT
CN8 = BSH-030-01-L-D-A-TR-60P-LDH
CN9 = 88511-180N-18P-L
CN10 = 50505-0040N-V01-4P-L
CN11 = 50519-00801-V01-8P-L
CN13 = 51586-03241-001-32P-L
CN14 = 50501-03001-001-30P-L
CN15 = SDCARD-PSDBTC-09GLBS1NN4H3-11P
CN17 = 50281-00401-001-4P-L
CN20 = 59012-0080N-003-8P-LDV-SMT
CN21 = RJ45-60414-08G67-12P
CN22 = MINIPCI-80053-1023-52P-SMT
CN24 = HDMI-HMRBL-AK520C-19P
CN25 CN28 = USB-YUSB0015-P002A-9P
CN26 = MINICARD-110021-52131-52P-RUV
CN27 = BAT-23_2-4_2
CN29 = MIPCI-APCI0020-P003H-75P-KM
D1-D8 D10 D11 PD1 PD2 PD4 PD7 PD8 PD11 = DSM
D9 = SOT323_213-2_1-1_3-2N7002W
D13 D14 = SOT323_213-2_1-1_3-3P
F1 = FSMD1206P150TS
FAN1 = 50273-0040L-001-4P-L
H1 H3 = H-TC236BC315D118P2
H2 = O-U83B-5
H5 H10 H11 = H-TC276BC197D142P2
H7 = H-C236D146P2
H8 = H-C98D98N
H9 = O-U83B-4
H12 = O-U83A-1
H13 = H-C236D118P2
H14 = INTEL-BKT-SHARK-ULT
H15 = H-TC256IC118BC315D118P2
H16 = H-TC236IC102BC236D102P2
H18 = O-Y12A-5
